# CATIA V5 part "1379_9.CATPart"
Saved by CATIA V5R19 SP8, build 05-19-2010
Part number: 9
Bounding box of the stored display mesh (mm): x -10.5 to 0, y -23 to 73, z -26 to 38.882
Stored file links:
  C:\Users\ThinkMotion\Desktop\EU_thinkMotion\iao\IAO_MMS_Groupe3\bblot\bblot\1379_9.CATPart
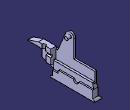
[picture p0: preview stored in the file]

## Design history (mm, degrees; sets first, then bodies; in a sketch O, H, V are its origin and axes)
Body1 (main body)
  Line1 to Line3: stored without definition
  Sketch1 on yz-plane, origin (0, 0, 0), H (0, 1, 0), V (0, 0, 1)
    line L1 (-8, 3) -> (-8, -12)
    point P2 (-8, -12)
    reference projected line E1 through (0, 0) direction (0, 1) from Line1
    line L2 (-8, 3) -> (-23, 3)
    reference projected line E2 through (0, 0) direction (1, 0) from Line2
    line L3 (-23, 3) -> (-23, 4)
    line L4 (-23, 4) -> (-8, 9)
    line L5 (-8, 9) -> (10, 9)
    line L6 (10, 9) -> (10, -6)
    line L7 (10, -6) -> (12, -6)
    line L8 (12, -6) -> (12, 8)
    line L9 (12, 8) -> (68, 8)
    line L10 (68, 8) -> (68, -7)
    line L11 (68, -7) -> (70, -12)
    line L12 (70, -12) -> (70, -23)
    line L13 (70, -23) -> (73, -23)
    line L14 (73, -23) -> (73, -26)
    line L15 (73, -26) -> (9, -26)
    line L16 (9, -26) -> (9, -23)
    line L17 (9, -23) -> (12, -23)
    line L18 (12, -23) -> (12, -19)
    line L19 (12, -19) -> (-8, -12)
    point P20 (-8, -12)
    reference projected line E3 through (0, 0) direction (1, 0) from Line3
    length L1 = 15
    distance E1 L1 = 8
    distance E2 L2 = 3
    length L2 = 15
    length L3 = 1
    length L4 H = 15
    length L4 V = 5
    length L5 = 18
    distance L8 L6 = 2
    distance E3 L7 = 6
    distance L12 L18 = 58
    distance L18 L10 = 56
    distance L1 L18 = 20
    distance L9 L5 = 1
    length L18 = 4
    distance L17 L15 = 3
    distance L9 L15 = 34
    length L17 = 3
    length L10 = 15
    length L12 = 11
    length L13 = 3
    vertical: L1 V, L3 V, L6 V, L8 V, L10 V, L12 V, L14 V, L16 V, L18 V
    horizontal: L2 H, L5 H, L7 H, L9 H, L13 H, L15 H, L17 H
    coincidence: L19 P2, P20 P2, L17 L13
  Pad1: profile Sketch1, direction (1, 0, 0), length 7.5, opposite side length 7.5
  Sketch2 on end face of Pad1, origin (7.5, 0, 0), H (0, 1, 0), V (0, 0, 1)
    line L1 (9, -23) -> (73, -23)
    line L2 (73, -23) -> (73, -26)
    line L3 (73, -26) -> (9, -26)
    line L4 (9, -26) -> (9, -23)
    reference projected line E1 (9, -26) -> (73, -26) from edge [face of Pad1 from Sketch1.L15 | end face of Pad1]
    reference projected line E2 (73, -26) -> (73, -23) from edge [face of Pad1 from Sketch1.L14 | end face of Pad1]
    reference projected line E3 (9, -23) -> (9, -26) from edge [face of Pad1 from Sketch1.L16 | end face of Pad1]
    reference projected line E4 (12, -23) -> (9, -23) from edge [face of Pad1 from Sketch1.L17 | end face of Pad1]
    horizontal: L1 H, L3 H
    vertical: L2 V, L4 V
    coincidence: L3 E1, L2 E2, L4 E3, L1 E4
  Pad2: profile Sketch2, direction (1, 0, 0), length 3
  Mirror1: of Pad2, about yz-plane
  Fillet1: radius 3, on edge [face of Mirror1 | face of Mirror1] (x3); edge [face of Mirror1 | end face of Pad2]
  Sketch3 on yz-plane, origin (0, 0, 0), H (0, 1, 0), V (0, 0, 1)
    line L1 (12, 8) -> (70, 8)
    line L2 (70, 8) -> (70, -12)
    line L3 (70, -12) -> (50, -12)
    line L4 (12, -16) -> (12, 8)
    point P3 (70, -12)
    point P4 (12, -16)
    reference projected point E1 (70, -12) from vertex [face of Pad1 from Sketch1.L11 | end face of Pad1 | face of Pad1 from Sketch1.L12]
    point P5 (12, -16)
    line L5 (12, -16) -> (20, -16)
    point P6 (20, -16)
    line L6 (20, -16) -> (20, -13)
    point P7 (20, -12)
    arc A1 centre (46, -12) radius 4 from (42, -12) to (50, -12) ccw
    point P8 (46, -12)
    point P9 (42, -12)
    point P10 (50, -12)
    reference projected line E2 (70, -23) -> (70, -12) from edge [face of Pad1 from Sketch1.L12 | end face of Pad1]
    line L7 (42, -12) -> (21, -12)
    reference projected line E3 (12, 8) -> (12, -6) from edge [face of Pad1 from Sketch1.L8 | end face of Pad1]
    reference projected line E4 (12, 8) -> (12, -6) from edge [face of Pad1 from Sketch1.L8 | end face of Pad1]
    reference projected line E5 (68, 8) -> (12, 8) from edge [face of Pad1 from Sketch1.L9 | end face of Pad1]
    arc A2 centre (21, -13) radius 1 from (20, -13) to (21, -12) cw
    radius A1 = 4
    distance E2 P10 = 20
    distance L6 E3 = 8
    distance P6 P7 = 4
    radius A2 = 1
    horizontal: L1 H, L3 H, L5 H, L7 H
    vertical: L2 V, L4 V, L6 V
    coincidence: P3 E1, P8 L3, P9 L3, L3 L7, L4 E4, P4 P5, L1 E5, L6 P7, L7 P7
    tangency: A2 L6, A2 L7
  Pocket1: profile Sketch3, direction (-1, 0, 0), length 2, opposite side length 1
  Sketch4 on yz-plane, origin (0, 0, 0), H (0, 1, 0), V (0, 0, 1)
    line L1 (12, 8) -> (68, 8)
    line L2 (68, 8) -> (68, -5)
    line L3 (68, -5) -> (12, -5)
    line L4 (12, -5) -> (12, 8)
    reference projected line E1 (68, 8) -> (12, 8) from edge [face of Pad1 from Sketch1.L9 | end face of Pad1]
    reference projected line E2 (12, 8) -> (12, -6) from edge [face of Pad1 from Sketch1.L8 | end face of Pad1]
    reference projected line E3 (68, -7) -> (68, 8) from edge [face of Pad1 from Sketch1.L10 | end face of Pad1]
    length L2 = 13
    horizontal: L1 H, L3 H
    vertical: L2 V, L4 V
    coincidence: L1 E1, E2 L4, L2 E3
  Pocket2: profile Sketch4, direction (-1, 0, 0), length 5, opposite side length 5
  Sketch5 on face of Pad1 from Sketch1.L6, origin (-1.3871, 10, 2.8871), H (1, 0, 0), V (0, 0, -1)
    point P1 (1.3871, 2.8871)
    reference projected point E1 (1.3871, 2.8871) from Line4
    coincidence: P1 E1
  Hole1: placed by Sketch5, at (0, 10, 0) direction (0, -1, 0), diameter 4, through (limit type 3)
  Sketch6 on face of Pad1 from Sketch1.L5, origin (-0.0769, 2.812, 9), H (1, 0, 0), V (0, 1, 0)
    point P1 (0.0769, -2.812)
    reference projected point E1 (0.0769, -2.812) from Line5
    coincidence: P1 E1
  Hole2: placed by Sketch6, at (0, 0, 9) direction (0, 0, -1), diameter 5, through (limit type 3)
  Sketch7 on yz-plane, origin (0, 0, 0), H (0, 1, 0), V (0, 0, 1)
    line L1 (-8, 3) -> (3, 3)
    line L2 (3, 3) -> (3, -10)
    line L3 (3, -10) -> (4, -11)
    line L4 (4, -11) -> (10, -11)
    line L5 (10, -11) -> (10, -6)
    line L6 (10, -6) -> (12, -6)
    line L7 (12, -6) -> (12, -19)
    line L8 (12, -19) -> (-8, -12)
    line L9 (-8, -12) -> (-8, 3)
    reference projected line E1 (-8, 3) -> (-8, -12) from edge [face of Pad1 from Sketch1.L1 | end face of Pad1]
    reference projected line E2 (-8, -12) -> (12, -19) from edge [face of Pad1 from Sketch1.L19 | end face of Pad1]
    reference projected line E3 (12, 8) -> (12, -6) from edge [face of Pad1 from Sketch1.L8 | end face of Pad1]
    reference projected line E4 (12, -6) -> (10, -6) from edge [face of Pad1 from Sketch1.L7 | end face of Pad1]
    reference projected line E5 (10, -6) -> (10, 9) from edge [face of Pad1 from Sketch1.L6 | end face of Pad1]
    reference projected line E6 (-23, 3) -> (-8, 3) from edge [face of Pad1 from Sketch1.L2 | end face of Pad1]
    length L5 = 5
    length L4 = 6
    angle L4 L3 = 135
    distance L2 L9 = 11
    horizontal: L1 H, L4 H, L6 H
    vertical: L2 V, L5 V, L7 V, L9 V
    coincidence: L9 E1, L8 E2, L7 E3, L6 E4, L5 E5, L1 E6
  Pocket3: profile Sketch7, direction (-1, 0, 0), length 5, opposite side length 5
  Point1: stored without definition
  Sketch8 on end face of Pocket2, origin (-5, 0, 0), H (0, 1, 0), V (0, 0, 1)
    line L1 (38, 33) -> (38, 8)
    line L2 (38, 8) -> (15, 8)
    line L3 (15, 8) -> (26.4675, 35.3221)
    arc A1 centre (32, 33) radius 6 from (26.4675, 35.3221) to (38, 33) cw
    point P5 (32, 33)
    reference projected line E1 (68, 8) -> (12, 8) from edge [face of Pad1 from Sketch1.L9 | end face of Pad1]
    reference projected point E2 (32, 33) from Point1
    radius A1 = 6
    length L2 = 23
    vertical: L1 V
    horizontal: L2 H
    tangency: A1 L3, A1 L1
    coincidence: L2 E1, E2 P5
  Pad3: profile Sketch8, direction (-1, 0, 0), up to start face of Pad1
  Sketch9 on face of Pocket2, origin (-5, 0, 0), H (0, 1, 0), V (0, 0, 1)
    circle A1 centre (32, 33) radius 2.5
    reference projected arc E1 centre (32, 33) radius 6 from (38, 33) to (26.4675, 35.3221) ccw from edge [face of Pad3 from Sketch8.A1 | start face of Pad3]
    radius A1 = 2.5
    concentricity: A1 E1
  Pad4: profile Sketch9, direction (1, 0, 0), length 10
  Split1: SplitPlane yz-plane
  Line4: stored without definition
  Line5: stored without definition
